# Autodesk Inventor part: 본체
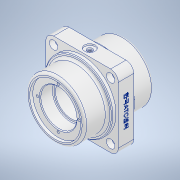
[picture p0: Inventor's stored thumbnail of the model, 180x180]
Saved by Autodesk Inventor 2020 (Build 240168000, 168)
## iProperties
Created: 2023-10
Part Number: 본체
Material: 알루미늄 6061
Document SubType Name: Modeling
Designer: oem
Density: 2.7 g/cm^3
Appearance: 알루미늄 - 평지
Mass: 945.786 g
Surface Area: 536.974 cm^2
Volume: 350.291 cm^3
Author: oem
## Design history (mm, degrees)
sketch "스케치1"
  geometry: L1 (-47, -47)-(47, -47); L2 (47, -47)-(47, 47); L3 (47, 47)-(-47, 47); L4 (-47, 47)-(-47, -47); L5 (-47, -47)-(47, 47); L6 (47, -47)-(-47, 47); 1 further point
  constraints: 12 end point, 2 midpoint, 2 parallel, 1 horizontal, 1 perpendicular
  dimensions: "d0" = 94 distance between parallel lines of L1 L3; "d1" = 94 distance between parallel lines of L2 L4
extrude "돌출1" new body sketch "스케치1" stored distance "d2" = 20; taper "d3" = 0 deg
sketch "스케치2"
  geometry: C1 r 44 at (0, 0); 1 further point
  constraints: 1 centre point, 1 coincident
  dimensions: "d4" = 88 diameter of C1
extrude "돌출2" join sketch "스케치2" distance "d5" = 5; taper "d6" = 0 deg
sketch "스케치3"
  geometry: C1 r 44 at (0, 0) reference; C2 r 38 at (0, 0)
  constraints: 1 centre point, 1 coincident
  dimensions: "d7" = 76 diameter of C2
extrude "돌출3" join sketch "스케치3" distance "d8" = 30; taper "d9" = 0 deg
node "작업 평면1"
sketch "스케치4"
  geometry: L1 (38, 45)-(-38, 45) reference; L2 (0, 45)-(0, -45); L3 (38, -45)-(-38, -45) reference; L4 (0, 45)-(33, 45); L5 (33, 45)-(33, 41); L6 (33, 41)-(23.5, 41); L7 (23.5, 41)-(23.5, 24); L8 (23.5, 24)-(20.5, 24); L9 (20.5, 24)-(20.5, -24); L10 (-47, -10)-(47, -10) reference; L11 (20.5, -24)-(23.5, -24); L12 (23.5, -24)-(23.5, -41); L13 (23.5, -41)-(33, -41); L14 (33, -41)-(33, -45); 3 further points
  constraints: 22 end point, 6 perpendicular, 6 point on line, 2 midpoint, 1 vertical
  dimensions: "d11" = 66 diameter of L5 L2; "d12" = 47 diameter of L7 L2; "d13" = 41 diameter of L9 L2; "d14" = 4 distance between parallel lines of L6 L4; "d15" = 17 distance between parallel lines of L8 L6; "d16" = 4 distance between parallel lines of L3 L13; "d17" = 17 distance between parallel lines of L13 L11
revolve "회전1" sketch "스케치4" stored, may be unused: angle "d18" = 90 deg
sketch "스케치5"
  geometry: C1 r 33 at (0, 0) reference; 1 further point
  constraints: 1 vertical alignment
  dimensions: "d19" = 27 distance of point (0, 27) C1.centre
hole "구멍1" sketch "스케치5" at (0, 27) diameter "d20" = 3.242; stored, may be unused: countersink angle "d24" = 90 deg, drill point angle "d26" = 118 deg; dims "d21" = 8, "d22" = 18, "d23" = 2, "d25" = 10
fillet "모깎기1" dims "d30" = 10
fillet "모깎기2" dims "d31" = 10
sketch "스케치7"
  geometry: A1 r 10 centre (-37, -37) between (-47, -37) and (-37, -47) reference; A2 r 10 centre (37, -37) between (37, -47) and (47, -37) reference; A3 r 10 centre (37, 37) between (47, 37) and (37, 47) reference; A4 r 10 centre (-37, 37) between (-37, 47) and (-47, 37) reference; 4 further points
  constraints: 4 coincident
hole "구멍2" sketch "스케치7" at (-37, 37), (37, 37), (37, -37), (-37, -37) diameter "d32" = 6.6; stored, may be unused: countersink angle "d36" = 90 deg, drill point angle "d38" = 118 deg; dims "d33" = 8, "d34" = 11, "d35" = 7, "d37" = 10
sketch "스케치8"
  geometry: C1 r 3.3 at (-37, 37) reference; A1 r 10 centre (37, -37) between (37, -47) and (47, -37) reference; A2 r 10 centre (37, 37) between (47, 37) and (37, 47) reference; A3 r 10 centre (-37, -37) between (-47, -37) and (-37, -47) reference; 4 further points
  constraints: 4 coincident
hole "구멍3" sketch "스케치8" at (37, 37), (-37, 37), (-37, -37), (37, -37) diameter "d39" = 6.6; stored, may be unused: countersink angle "d43" = 90 deg, drill point angle "d45" = 118 deg; dims "d40" = 8, "d41" = 11, "d42" = 7, "d44" = 10
node "작업 평면2"
sketch "스케치9"
  geometry: 2 further points
  constraints: 1 coincident, 1 other
feature "엠보싱1" sketch "스케치9" dims "d0" = 94, "d1" = 94, "d47" = 0.5, "d48" = 0
chamfer "모따기1" distance "d77" = 1; stored, may be unused: second distance "d78" = 2, angle "d79" = 45 deg
fillet "모깎기3" dims "d80" = 1
fillet "모깎기4" dims "d81" = 3
sketch "스케치15"
  geometry: 2 further points
  constraints: 1 coincident
hole "구멍8" sketch "스케치15" at (37, 10) diameter "d82" = 5.1881; stored, may be unused: countersink angle "d86" = 90 deg, drill point angle "d88" = 0 deg; dims "d83" = 12, "d84" = 7, "d85" = 4, "d87" = 12
sketch "스케치16"
  geometry: C1 r 3.5 at (37, 10) reference; C2 r 2.594 at (37, 10) reference; C3 r 7 at (37, 10)
  constraints: 1 centre point, 1 coincident
  dimensions: "d89" = 14 diameter of C3
extrude "돌출4" cut sketch "스케치16" distance "d90" = 2; taper "d91" = 0 deg
node "솔리드1"
mirror "미러1"
pattern_circular "원형 패턴1" dims angle "d28" = 360 deg
mirror "미러2"
feature "A9D066F2-1C7D-4E18-AEED-F7BC21143FA4" dims "d32" = 6.6, "d33" = 8, "d34" = 11, "d35" = 7, "d36" = 90 deg, "d37" = 10, "d38" = 118 deg
other parameters: "d10" = 0, "d46" = 164.5
